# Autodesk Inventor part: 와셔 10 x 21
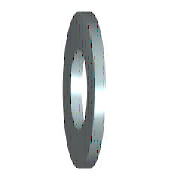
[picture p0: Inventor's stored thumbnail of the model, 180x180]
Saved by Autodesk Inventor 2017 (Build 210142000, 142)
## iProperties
Created: 2012-02
Part Number: 와셔 10 x 21
Material: 강철, 연강
Description: 평면 와셔
Document SubType Name: Modeling
Standard: KS B 1326
Designer: mduedu
Standards Organization: KS
Language: ko-KR
Size Designation: 10x21
Categories: <MemberInstance><Categories><Category DisplayName="조임쇠" InternalName="e4da775c-781d-43d5-af7c-5136215cf5a6" Mnemonic="FSTN"><Category DisplayName="와셔" InternalN
Density: 1 g/cm^3
Appearance: 파란색 - 벽 페인트 - 광택
IsCustomPart: 1
Author: mduedu
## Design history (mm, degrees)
sketch "스케치"
  geometry: C1 r 10.5 at (0, 0); C2 r 5.25 at (0, 0); 1 further point
  constraints: 2 centre point, 2 coincident
  dimensions: "d0" = 10.5 diameter of C2 (= SD1); "d1" = 21 diameter of C1 (= SD2)
extrude "본체" new body sketch "스케치" distance "d2" = 2 (= SD); taper "d3" = 0 deg
workaxis "Work Axis1"
workplane "Work Plane1"
body "Solid1"
other parameters: "SD1" = 10.5 [user parameter; used in 1 equation term], "SD2" = 21 [user parameter; used in 1 equation term], "SD" = 2 [user parameter; used in 1 equation term], "d4" = 0, "d5" = 0, "d6" = 0, "d7" = 0
